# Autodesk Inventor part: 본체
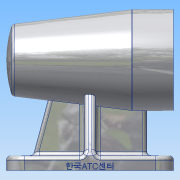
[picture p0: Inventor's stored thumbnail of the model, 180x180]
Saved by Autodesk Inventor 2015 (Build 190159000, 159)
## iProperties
Created: 2018-09
Part Number: 본체
Material: 알루미늄 6061
Document SubType Name: Modeling
Designer: user
Density: 2.7 g/cm^3
Appearance: 알루미늄 - 평지
Mass: 733.557 g
Surface Area: 666.939 cm^2
Volume: 271.688 cm^3
Author: user
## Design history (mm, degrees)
sketch "스케치2"
  geometry: L1 (56, 35)-(56, -35); L2 (56, -35)-(-56, -35); L3 (-56, -35)-(-56, 35); L4 (-56, 35)-(56, 35); L5 (56, 35)-(-56, -35); L6 (56, -35)-(-56, 35); 1 further point
  constraints: 12 end point, 2 midpoint, 2 parallel, 1 perpendicular, 1 vertical
  dimensions: "d15" = 70 distance of L1.start L1.end; "d16" = 112 distance of L1.end L2.end
extrude "돌출1" new body sketch "스케치2" distance "d17" = 10; taper "d18" = 0 deg
revolve "회전2" stored, may be unused: angle "d27" = 90 deg
sketch "스케치4"
  geometry: L1 (56, 10)-(-56, 10) reference; L2 (-56, 0)-(56, 0) reference; L3 (-52.27, 49.856)-(-52.27, 98.144) reference; L4 (28, 40)-(28, 108) reference; L5 (28, 40)-(28, 108) reference; L6 (56, 40)-(56, 108) reference; L7 (-52.27, 49.856)-(28, 40) reference; L8 (-38, 10)-(-20.851, 74); L9 (28, 40)-(56, 40) reference; L10 (-38, 10)-(38, 10); L11 (38, 10)-(38, 74); L12 (56, 74)-(-52.27, 74); 1 further point
  constraints: 8 end point, 4 point on line, 2 midpoint, 1 horizontal, 1 perpendicular
  dimensions: "d28" = 18 distance of L1.start L10.end; "d29" = 18 distance of L1.end L8.start; "d30" = 105 deg angle of L1 L8
extrude "돌출2" join sketch "스케치4" stored distance "d31" = 8; taper "d32" = 0 deg
sketch "스케치6"
  geometry: L1 (10, -35)-(10, 35) reference; L2 (47.177, 4)-(10, 4) reference; L3 (10, -4)-(47.177, -4) reference; L4 (47.177, 4)-(40.236, 4) reference; L5 (40.236, -4)-(47.177, -4) reference; L6 (10, 35)-(74, 11.706); L7 (10, -35)-(74, -11.706); L8 (74, 0)-(74, -24.144); L9 (74, 0)-(74, 24.144); L10 (0, -35)-(10, -35) reference; L11 (0, 35)-(10, 35) reference; L12 (10, 35)-(10, -35); L13 (74, 11.706)-(74, -11.706); A1 r 34 centre (74, 0) between (40.236, -4) and (40.236, 4) reference; A2 r 24.144 centre (74, 0) between (74, -24.144) and (74, 24.144) reference; 2 further points; 1 other entity
  constraints: 12 end point, 2 collinear, 2 point on circle, 2 point on line, 2 vertical, 1 other
  dimensions: "d33" = 20 deg angle of L10 L7; "d34" = 20 deg angle of L11 L6
extrude "돌출3" join sketch "스케치6" stored distance "d35" = 8; taper "d36" = 0 deg
revolve "회전3" stored, may be unused: angle "d55" = 90 deg
sketch "스케치7"
  geometry: C1 r 21 at (0, 0) reference; 2 further points
  constraints: 1 vertical alignment
  dimensions: "d56" = 26 distance of C1.centre point (0, 26)
hole "구멍1" sketch "스케치7" at (0, 26) diameter "d57" = 3.242; stored, may be unused: countersink angle "d61" = 90 deg, drill point angle "d63" = 118 deg; dims "d58" = 8, "d59" = 4, "d60" = 2, "d62" = 11
sketch "스케치8"
  geometry: L1 (-56, 35)-(-56, -35) reference; L2 (-56, -35)-(-4, -35) reference; 3 further points
  dimensions: "d67" = 12 distance from line of L1 point (-44, 23); "d68" = 12 horizontal distance of L1.start point (-44, 23); "d69" = 12 horizontal distance of L1.end point (-44, -23); "d70" = 12 distance from line of point (-44, -23) L2
hole "구멍2" sketch "스케치8" at (-44, 23), (-44, -23) diameter "d71" = 5.5; stored, may be unused: countersink angle "d75" = 90 deg, drill point angle "d77" = 0 deg; dims "d72" = 8, "d73" = 9.5, "d74" = 5.4, "d76" = 11
sketch "스케치9"
  geometry: L1 (112, 0)-(0, 0) reference; L2 (112, 0)-(112, 10) reference; 2 further points
  constraints: 1 other
  dimensions: "d78" = 3 distance from line of L1 point (56, 3); "d79" = 56 distance from line of L2 point (56, 3)
feature "엠보싱1" sketch "스케치9" dims "d15" = 70, "d16" = 112, "d80" = 0.5, "d81" = 0
fillet "모깎기1" dims "d82" = 12
fillet "모깎기4" dims "d85" = 3
chamfer "모따기1" distance "d86" = 1; stored, may be unused: second distance "d87" = 2, angle "d88" = 45 deg
fillet "모깎기8" dims "d92" = 3
fillet "모깎기11" dims "d96" = 3
fillet "모깎기12" dims "d97" = 3
fillet "모깎기13" dims "d98" = 3
fillet "모깎기14" dims "d99" = 3
node "솔리드2"
sketch "스케치3"
  geometry: L1 (56, 0)-(56, 74); L2 (56, 74)-(56, 108); L3 (56, 108)-(28, 108); L4 (28, 108)-(-52.27, 98.144); L5 (-56, 74)-(56, 74); L6 (56, 95)-(41, 95); L7 (41, 95)-(41, 95); L8 (38, 98)-(-10, 98); L9 (-13, 95)-(-13, 95); L10 (-25, 94.7)-(-25, 91.5); L11 (-25, 91.5)-(-42.7, 91.5); L12 (-43, 91.2)-(-43, 90); L13 (-43, 90)-(-46.7, 90); L14 (-13, 95)-(-24.7, 95); L15 (-47, 89.7)-(-47, 84.5); L16 (-47, 84.5)-(-47, 84.5); L17 (-50, 81.5)-(-50, 74); L18 (-56, 74)-(-56, 114.599); A1 r 80 centre (24, 74) between (-52.27, 98.144) and (-56, 74); A2 r 0.3 centre (-46.7, 89.7) between (-46.7, 90) and (-47, 89.7); A3 r 0.3 centre (-42.7, 91.2) between (-42.7, 91.5) and (-43, 91.2); A4 r 0.3 centre (-24.7, 94.7) between (-24.7, 95) and (-25, 94.7); A5 r 3 centre (-10, 95) between (-10, 98) and (-13, 95); A6 r 3 centre (38, 95) between (41, 95) and (38, 98); A7 r 3 centre (-47, 81.5) between (-47, 84.5) and (-50, 81.5); 6 further points
  constraints: 36 end point, 16 point on line, 14 point on circle, 13 tangent, 8 perpendicular, 7 centre point, 5 vertical, 3 horizontal, 2 equal radius
  dimensions: "d19" = 74 distance of L1.start L1.end; "d21" = 34 distance of L1.end L2.end; "d22" = 28 distance of L2.end L3.end; "d25" = 7 deg angle of L3 L4; "d26" = 80 radius of A1; "d37" = 21 distance of L1.end L6.start; "d38" = 15 distance of L6.start L6.end; "d39" = 54 distance of point (41, 98) point (-13, 98); "d41" = 12 distance of L9.end point (-25, 95); "d43" = 18 distance of L10.end point (-43, 91.5); "d44" = 24 distance between parallel lines of L5 L8; "d45" = 17.5 distance between parallel lines of L5 L11; "d48" = 3 distance of L15.end point (-50, 84.5); "d49" = 10.5 distance of point (-50, 84.5) L17.end; "d50" = 16 distance between parallel lines of L5 L13; "d51" = 4 distance of L12.end point (-47, 90); "d52" = 0.3 radius of A2; "d53" = 0.3 radius of A4; "d54" = 3 radius of A5; "d93" = 3 radius of A7; "d101" = 112 distance of L1.end L5.start
pattern_circular "원형 패턴1" dims angle "d65" = 360 deg
mirror "대칭1"
node "투영된 루프1"
node "투영된 루프2"
node "투영된 루프3"
